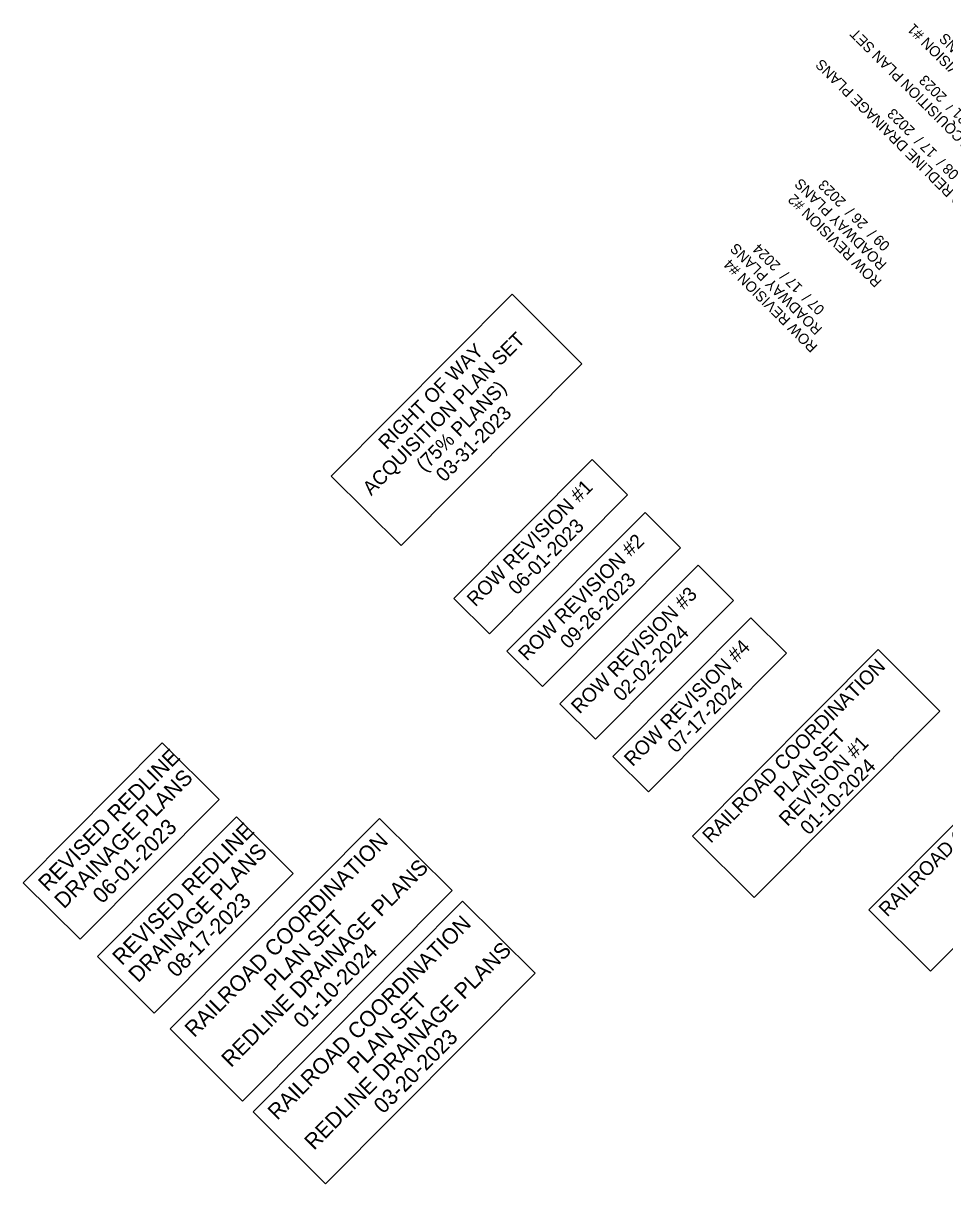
# Model space of a CAD drawing. Extents: x 1481763 to 1495577, y 493394 to 506245.
# Drawn here: x 1481763 to 1484845, y 493394 to 497274 of the extents above; entities that cross this region are included whole.
import ezdxf

# ---------------------------------------------------------------- set-up
doc = ezdxf.new("R2010")
doc.units = 0
for name, color, linetype in [('Prop Plan Preparation Drainage Notes Label', 7, 'Continuous'), ('Prop Shade Medium', 7, 'Continuous'), ('Sheet Sticker Incomplete CELL', 7, 'Continuous')]:
    doc.layers.add(name, color=color, linetype=linetype)

msp = doc.modelspace()

# ---------------------------------------------------------------- linework, layer by layer
at = {"layer": 'Prop Plan Preparation Drainage Notes Label'}
for points in [[(1481952.9, 494211.3), (1481762.8, 494400.6), (1482228.1, 494867.8), (1482418.2, 494678.5)], [(1482200.9, 493964.3), (1482010.8, 494153.6), (1482476.1, 494620.8), (1482666.2, 494431.5)], [(1482496.2, 493670.2), (1482254, 493911.4), (1482954.9, 494615.1), (1483197, 494373.9)], [(1482773.8, 493393.8), (1482531.6, 493634.9), (1483232.5, 494338.7), (1483474.6, 494097.5)]]:
    msp.add_lwpolyline(points, close=True, dxfattribs=at)
at = {"layer": 'Prop Shade Medium'}
for points in [[(1481762.8, 494400.6), (1482228.1, 494867.8), (1482418.2, 494678.5), (1481952.9, 494211.3)], [(1482010.8, 494153.6), (1482476.1, 494620.8), (1482666.2, 494431.5), (1482200.9, 493964.3)], [(1482254, 493911.4), (1482954.9, 494615.1), (1483197, 494373.9), (1482496.2, 493670.2)], [(1482531.6, 493634.9), (1483232.5, 494338.7), (1483474.6, 494097.5), (1482773.8, 493393.8)]]:
    msp.add_lwpolyline(points, close=True, dxfattribs=at)
at = {"layer": 'Sheet Sticker Incomplete CELL'}
for points in [[(1483026.4, 495527.7), (1482792.7, 495760.4), (1483397.7, 496368), (1483631.4, 496135.2)], [(1483322.1, 495233.2), (1483203.5, 495351.3), (1483665.5, 495815.2), (1483784.1, 495697)], [(1483499.3, 495056.7), (1483380.7, 495174.9), (1483842.6, 495638.8), (1483961.2, 495520.6)], [(1483676.4, 494880.3), (1483557.8, 494998.5), (1484019.8, 495462.3), (1484138.4, 495344.2)], [(1483853.6, 494703.9), (1483735, 494822), (1484196.9, 495285.9), (1484315.5, 495167.8)], [(1484207.9, 494351.1), (1484001.5, 494556.6), (1484622.1, 495179.8), (1484828.5, 494974.3)], [(1484797.8, 494104.4), (1484591.5, 494309.9), (1485212.1, 494933.1), (1485418.4, 494727.6)]]:
    msp.add_lwpolyline(points, close=True, dxfattribs=at)

# ---------------------------------------------------------------- texts
at = {"layer": 'Prop Plan Preparation Drainage Notes Label'}
for s, height, rotation, p in [('REVISED REDLINE DRAINAGE PLANS', 35.009, 135.1191, (1485033.1, 496560.6)), ('08 /  17 /  2023', 35.009, 135.1191, (1484895.2, 496772.1)), ('REVISED REDLINE', 52.514, 45.1191, (1481845.1, 494368.2)), ('DRAINAGE PLANS', 52.514, 45.1191, (1481898.9, 494310.6)), ('06-01-2023', 52.51, 45.1191, (1482026.9, 494327.5)), ('REVISED REDLINE', 52.514, 45.1191, (1482093.1, 494121.2)), ('RAILROAD COORDINATION', 52.514, 45.1191, (1482334.8, 493880.6)), ('DRAINAGE PLANS', 52.514, 45.1191, (1482146.9, 494063.6)), ('REDLINE DRAINAGE PLANS', 52.514, 45.1191, (1482457.6, 493780.6)), ('08-17-2023', 52.51, 45.1191, (1482274.9, 494080.5)), ('PLAN SET', 52.51, 45.1191, (1482600.3, 494035.5)), ('RAILROAD COORDINATION', 52.514, 45.1191, (1482612.4, 493604.1)), ('01-10-2024', 52.51, 45.1191, (1482698.3, 493910.6)), ('REDLINE DRAINAGE PLANS', 52.514, 45.1191, (1482735.2, 493504.1)), ('PLAN SET', 52.51, 45.1191, (1482877.9, 493759.1)), ('03-20-2023', 52.51, 45.1191, (1482966.8, 493625.1))]:
    msp.add_text(s, height=height, rotation=rotation, dxfattribs=at).set_placement(p)
at = {"layer": 'Sheet Sticker Incomplete CELL'}
for s, height, rotation, p in [('REVISED ROW REVISION #1', 35.009, 135.1191, (1485191, 496828.1)), ('RIGHT OF WAY ACQUISITION PLAN SET', 35.009, 135.1191, (1485187.3, 496625)), ('ROADWAY PLANS', 35.009, 135.1191, (1485137.1, 496956)), ('03 /  31 /  2023', 35.009, 135.1191, (1485001.7, 496883.9)), ('ROADWAY PLANS', 35.009, 135.1191, (1484653.4, 496470.2)), ('09 /  26 /  2023', 35.009, 135.1191, (1484664.2, 496533.6)), ('ROW REVISION #2', 35.009, 135.1191, (1484636.9, 496412.5)), ('ROADWAY PLANS', 35.009, 135.1191, (1484437.9, 496253.5)), ('07 /  17 /  2024', 35.009, 135.1191, (1484445.6, 496320)), ('ROW REVISION #4', 35.009, 135.1191, (1484422.1, 496195.1)), ('ACQUISITION PLAN SET', 47.263, 45.1191, (1482926.6, 495692.6)), ('RIGHT OF WAY ', 47.263, 45.1191, (1482979.2, 495845.9)), ('(75% PLANS)', 47.263, 45.1191, (1483105.3, 495771.6)), ('03-31-2023', 47.26, 45.1191, (1483171.5, 495737.6)), ('ROW REVISION #1', 47.263, 45.1191, (1483274.8, 495321)), ('06-01-2023', 47.26, 45.1191, (1483413.6, 495359.9)), ('ROW REVISION #2', 47.263, 45.1191, (1483447.1, 495139.7)), ('09-26-2023', 47.26, 45.1191, (1483586.7, 495179.5)), ('ROW REVISION #3', 47.263, 45.1191, (1483623.7, 494962.7)), ('02-02-2024', 47.26, 45.1191, (1483764.5, 495003.7)), ('ROW REVISION #4', 47.263, 45.1191, (1483801, 494786.5)), ('RAILROAD COORDINATION', 47.263, 45.1191, (1484062.7, 494530.3)), ('07-17-2024', 47.26, 45.1191, (1483945.7, 494831.3)), ('PLAN SET', 47.26, 45.1191, (1484301.6, 494669.7)), ('RAILROAD COORDINATION', 47.263, 45.1191, (1484652.6, 494283.5)), ('REVISION #1', 47.263, 45.1191, (1484318.9, 494586.6)), ('01-10-2024', 47.26, 45.1191, (1484389.8, 494557.3))]:
    msp.add_text(s, height=height, rotation=rotation, dxfattribs=at).set_placement(p)

doc.saveas('drawing.dxf')
